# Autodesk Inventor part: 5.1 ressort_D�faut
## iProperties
Created: 2011-01
Part Number: 5.1 ressort_D�faut
Document SubType Name: Modeling
Designer: eric
Density: 1 g/cm^3
Mass: 3.95849 g
Surface Area: 45.5193 cm^2
Volume: 3.95849 cm^3
Author: eric
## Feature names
1. Base1
